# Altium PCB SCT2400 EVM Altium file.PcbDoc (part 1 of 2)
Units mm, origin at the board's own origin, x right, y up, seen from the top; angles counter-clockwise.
Board outline 45.2 x 80.2 mm, 4 copper layers (Top Layer, Signal Layer 1, Signal Layer 2, Bottom Layer), stack 0.778 mm thick; 165 components, 146 nets, 619 pads, 674 vias.
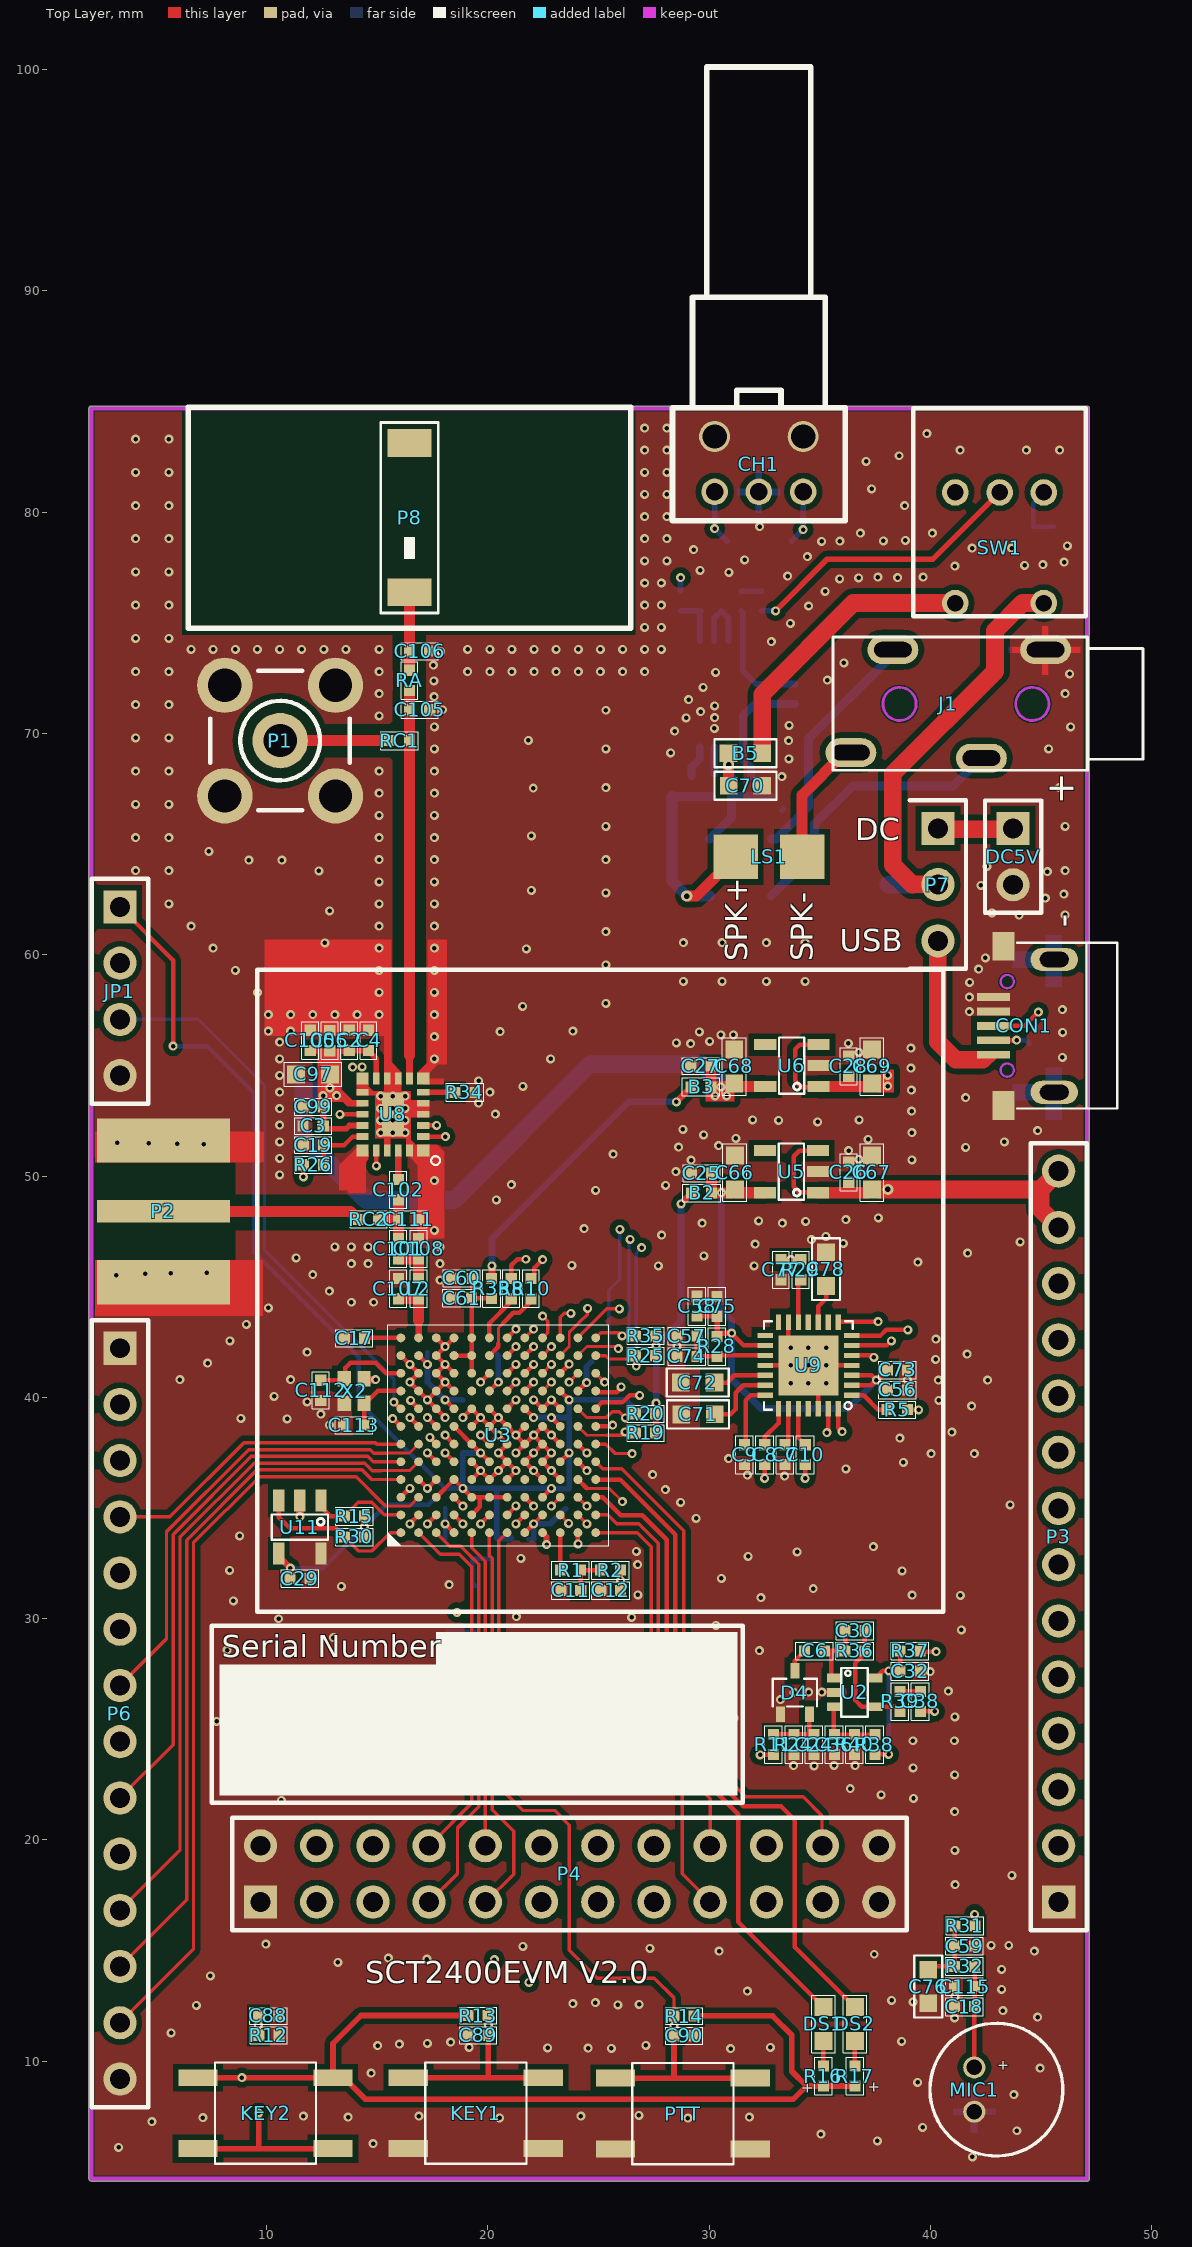
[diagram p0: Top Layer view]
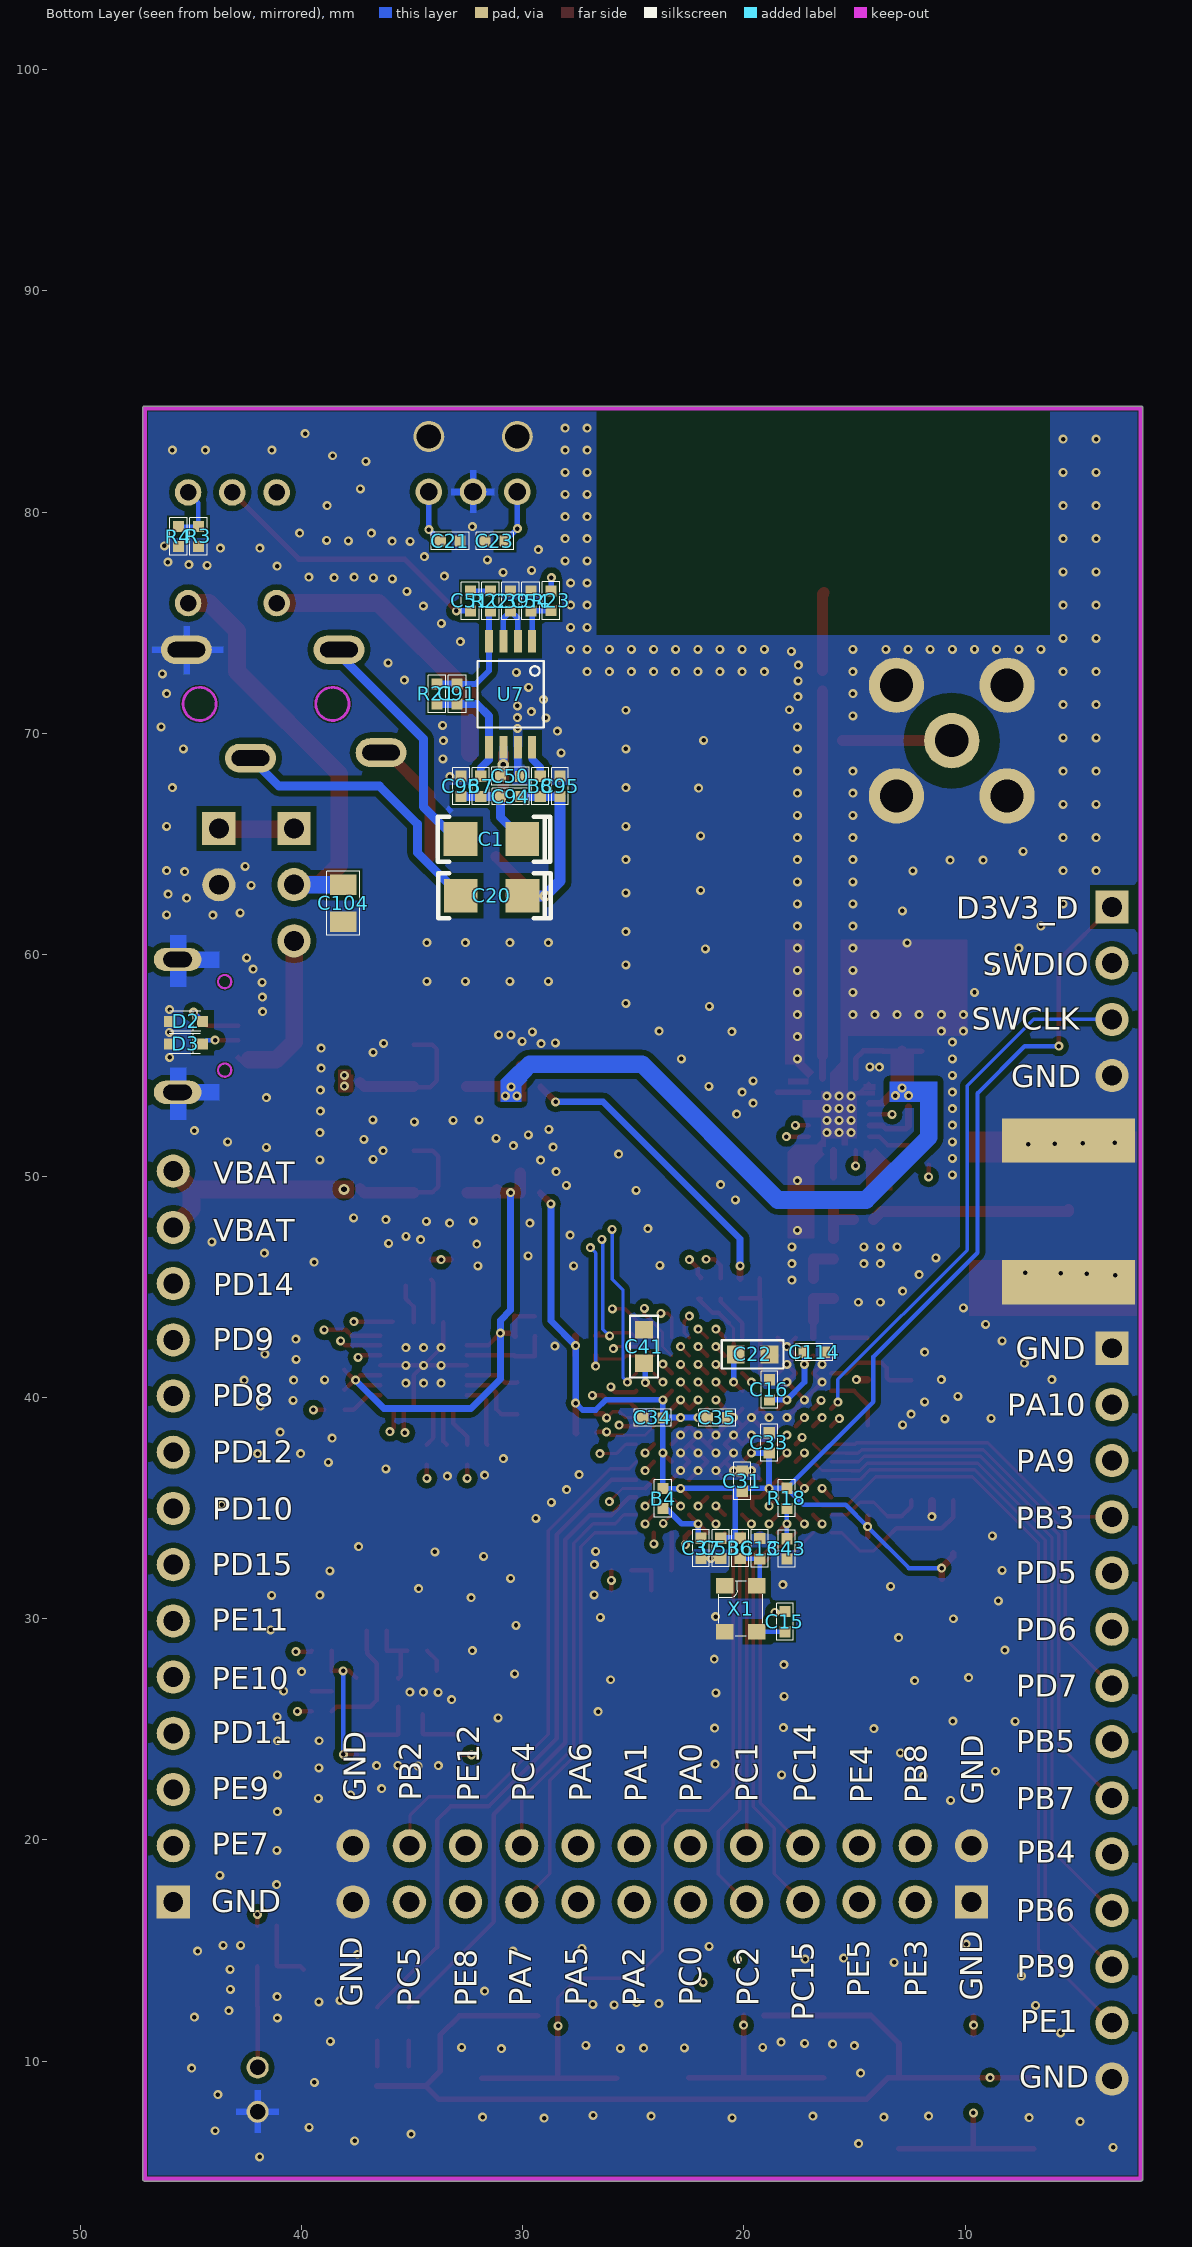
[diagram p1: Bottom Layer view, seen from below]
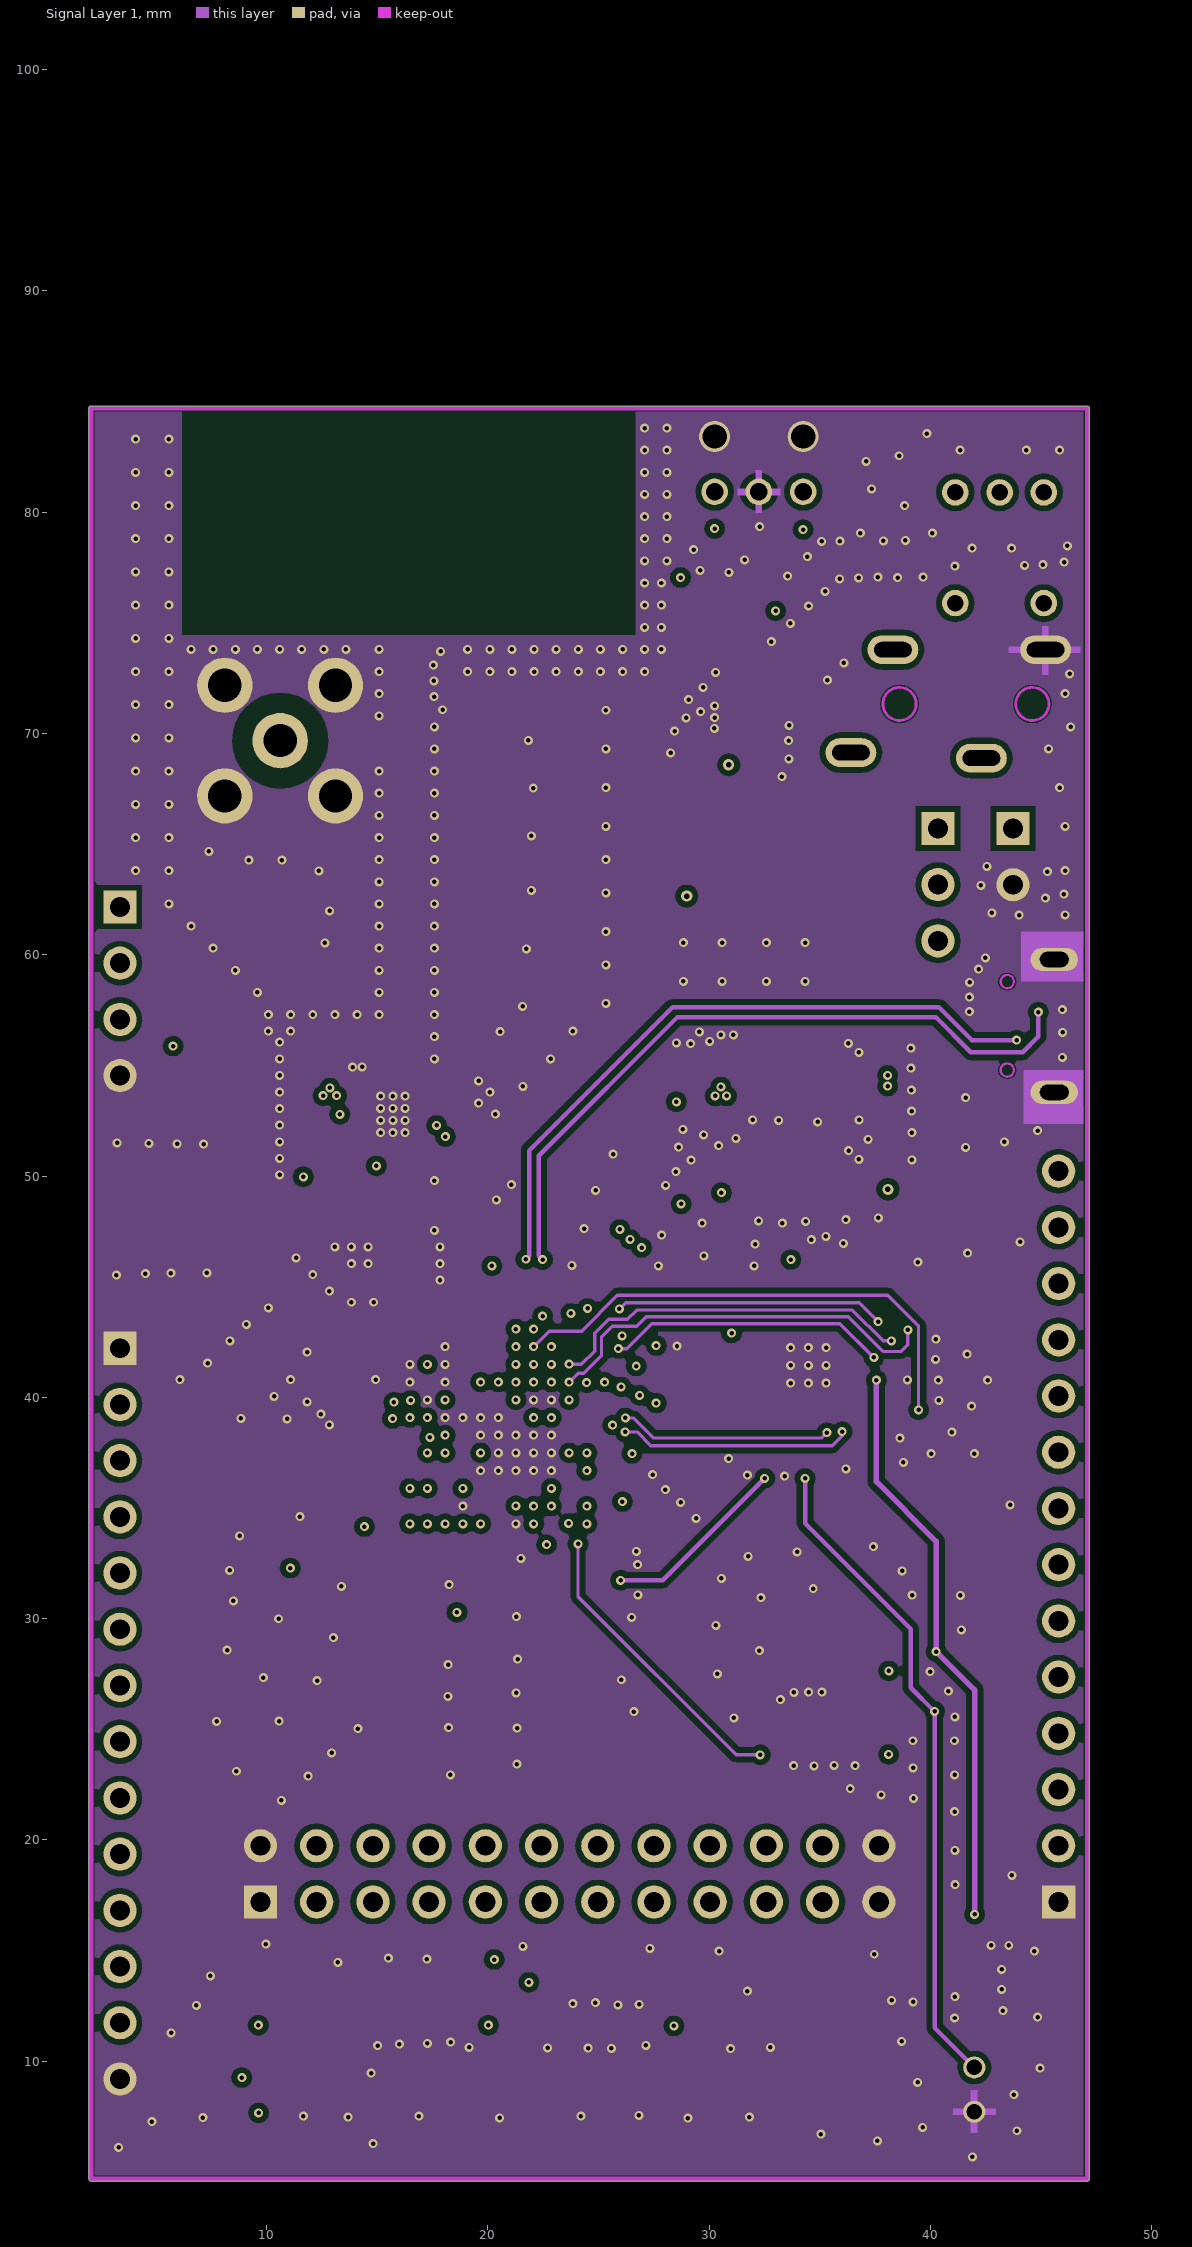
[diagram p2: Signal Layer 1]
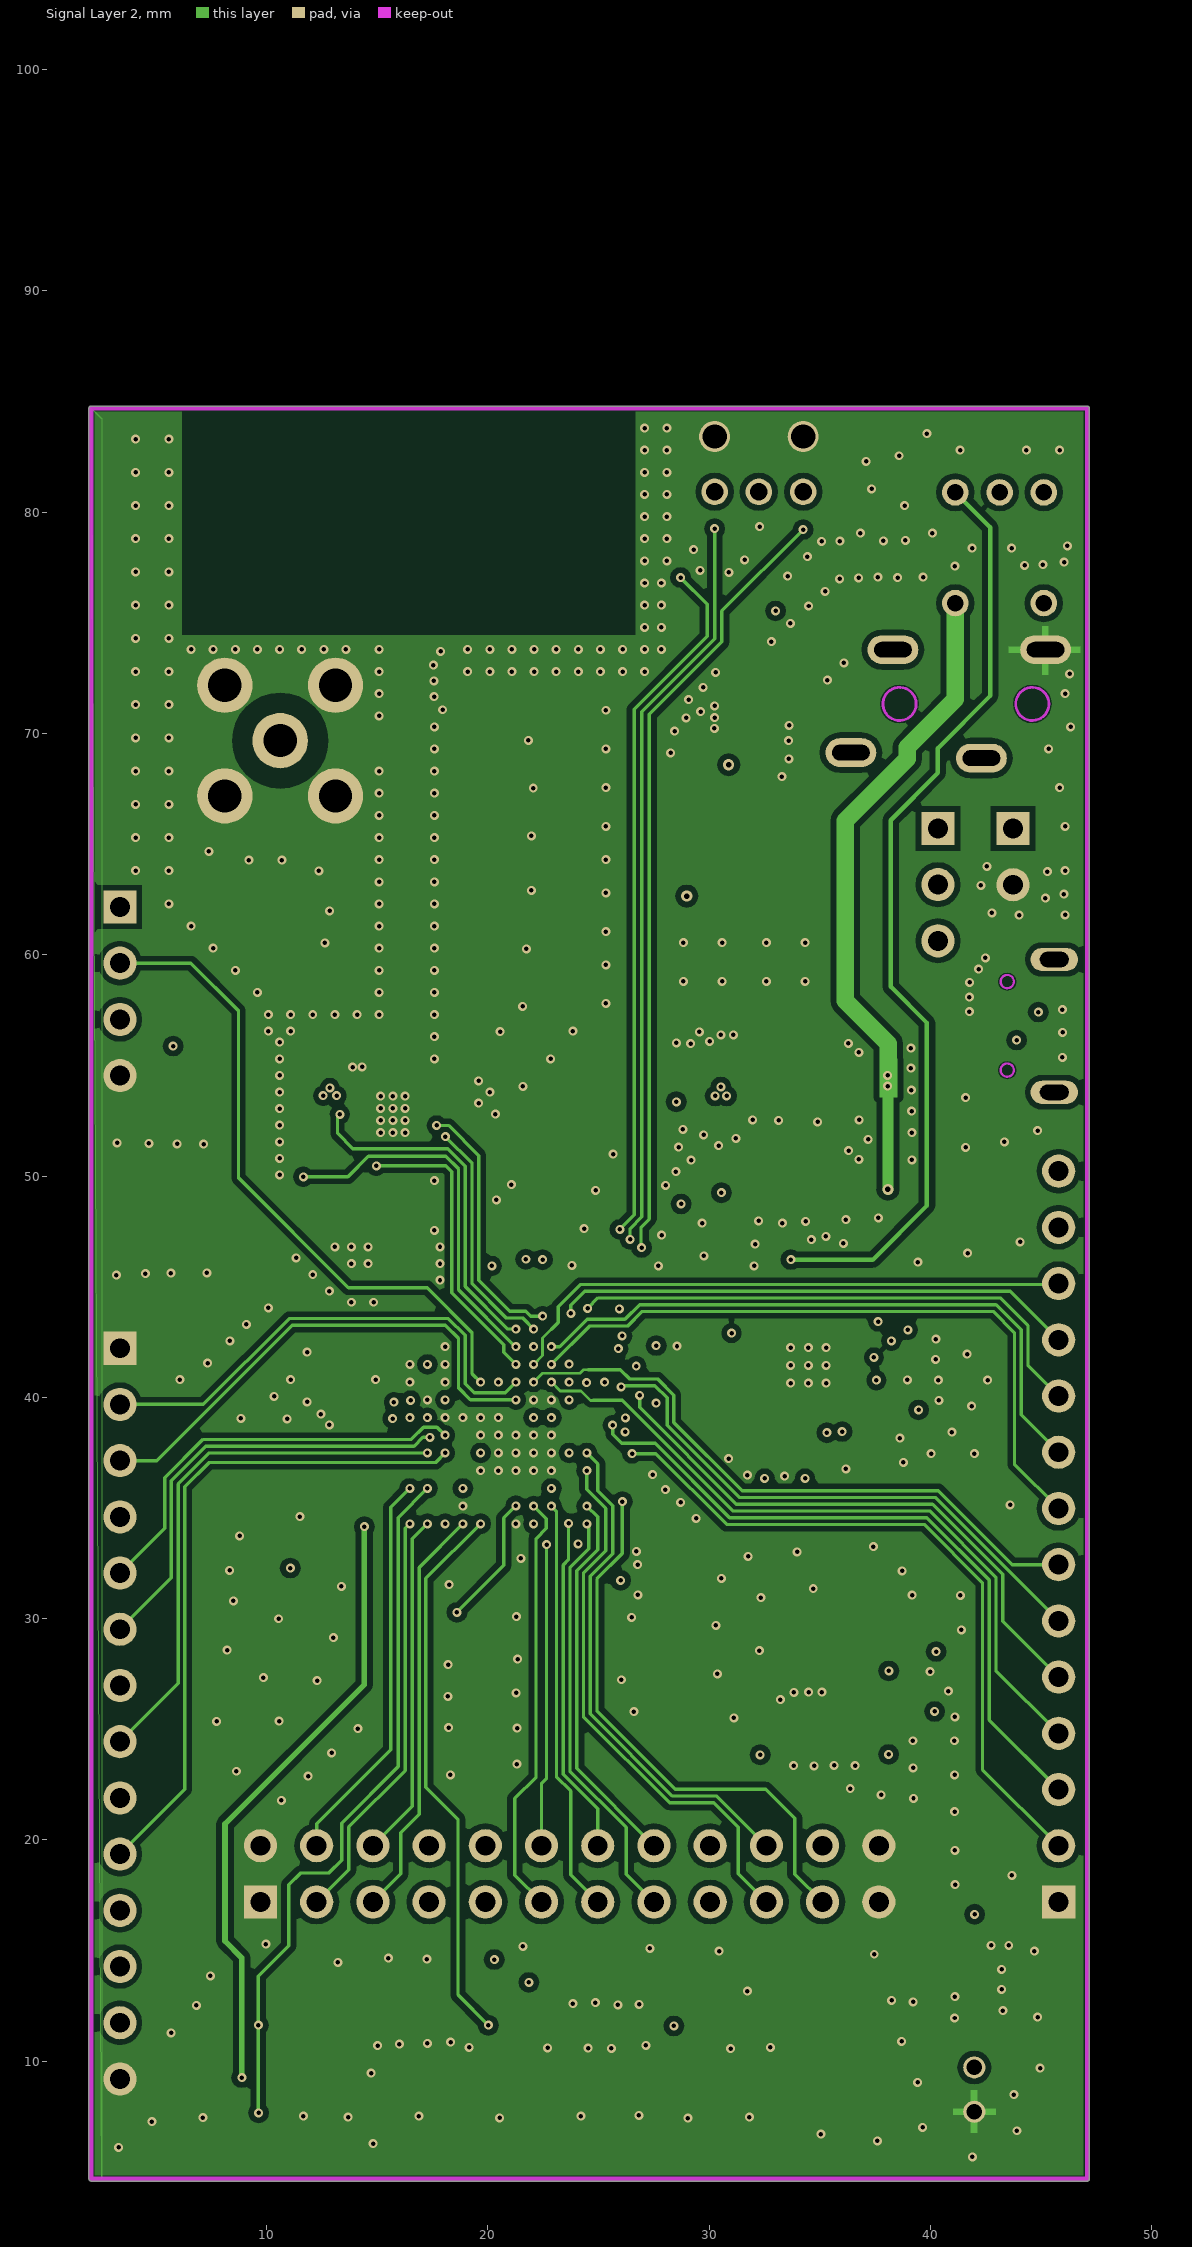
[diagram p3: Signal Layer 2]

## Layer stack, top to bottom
Top Solder: solder mask 0.0102, Solder Resist, Dk 3.5
Top Layer: signal copper 0.0356
Dielectric 1: core 0.254, FR-4, Dk 4.2
Signal Layer 1: signal copper 0.036
Dielectric 3: prepreg 0.127, Dk 4.2
Signal Layer 2: signal copper 0.036
Dielectric 2: core 0.254, Dk 4.2
Bottom Layer: signal copper 0.0356
Bottom Solder: solder mask 0.0102, Solder Resist, Dk 3.5

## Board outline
1.972,4.691 ccw(c2.074,4.691) 2.074,4.589 47.074,4.589 ccw(c47.074,4.691) 47.176,4.691 47.176,84.691 ccw(c47.074,84.691) 47.074,84.793 2.074,84.793 ccw(c2.074,84.691) 1.972,84.691

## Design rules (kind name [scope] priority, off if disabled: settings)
Clearance RF [All vs (OnLayer('Keep-Out Layer'))] p1: gap=0.051
Clearance [All] p2 off: gap=0.254
Clearance DRC [All] p3: gap=0.152 except(0.127: Track-SMDPad Track-Via)
ComponentClearance [All] p1: gap=0.051 collisioncheckmode=3 verticalgap=0.254 showdistances=FALSE
HoleSize [All] p1 off: absolutevalues=TRUE maxlimit=2.54 minlimit=0.025 maxpercent=80.000 minpercent=20.000
HoleToHoleClearance [All] p1 off: gap=0.254 allowstackedmicrovias=TRUE
MinimumSolderMaskSliver [All] p1 off: minsoldermaskwidth=0.254
PolygonConnect [All] p1: connectstyle=Direct reliefconductorwidth=0.254 reliefentries=4 polygonreliefangle="90 Angle" airgapwidth=0.254
RoutingVias [All] p1: holewidth=0.203 width=0.406 viastyle="Through Hole" minholewidth=0.203 minwidth=0.406 maxholewidth=0.508 maxwidth=1.27
SilkToBoardRegionClearance [All] p1 off:
SilkToSilkClearance [All] p1 off: silktosilkclearance=0.051
SilkToSolderMaskClearance [IsPad] p1 off: minsilkscreentomaskgap=0.254 clearancetoexposedcopper=TRUE
SolderMaskExpansion [All] p1: expansion=0.051
Width [All] p1: maxlimit=1.524 minlimit=0.127 preferedwidth=0.203
23 further rules are at their usual default settings.

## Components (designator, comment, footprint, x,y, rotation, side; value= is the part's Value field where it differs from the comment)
B2 "B601" 0402_MJ 30.111,49.241 r180 top
B3 "B601" 0402_MJ 30.084,54.033 r180 top
B4 "B601" 0402_MJ 23.659,35.874 r270 bottom
B5 "B601" 0603-mini 31.637,69.103 r0 top
B6 "NC" 0402 20.171,33.176 r90 bottom
B7 "B601" 0402 31.893,67.606 r270 bottom
B8 "B601" 0402 29.201,67.606 r270 bottom
C1 "100uF" C3216 26.574,65.215 r0 bottom
C2 "0.1uF" 0402 13.733,56.127 r90 top
C3 "1nF" 0402 12.102,52.265 r0 top
C4 "1nF" 0402 14.606,56.127 r90 top
C6 "47nF" 0402_MJ 34.306,28.541 r0 top
C7 "1uF" 0402_MJ 33.423,36.958 r90 top
C8 "1uF" 0402_MJ 32.509,36.958 r90 top
C9 "1uF" 0402_MJ 31.594,36.958 r90 top
C10 "1uF" 0402_MJ 34.338,36.958 r90 top
C11 "4.7nF" 0402_mj 23.294,31.278 r0 top
C12 "10nF" 0402_mj 25.097,31.278 r0 top
C13 "NC" 0402 19.292,33.17 r90 bottom
C15 "NC" 0402 18.149,29.867 r270 bottom
C16 "10nF" 0402 18.849,40.34 r90 bottom
C17 "10nF" 0402 13.963,42.668 r0 top
C18 "10nF" 0402_MJ 41.977,12.469 r180 top
C19 "1nF" 0402 12.113,51.401 r180 top
C20 "100uF" C3216 26.565,62.648 r0 bottom
C21 "100pF" 0402_MJ 33.725,78.694 r180 bottom
C22 "2.2uF" 0603_MJ 19.61,41.939 r0 bottom
C23 "100pF" 0402_MJ 30.804,78.694 r0 bottom
C24 "1uF" 0402_MJ 34.738,24.757 r270 top
C25 "0.1uF" 0402 29.658,50.133 r180 top
C26 "0.1uF" 0402 36.309,50.174 r90 top
C27 "0.1uF" 0402 29.627,54.973 r180 top
C28 "0.1uF" 0402 36.306,54.969 r90 top
C29 "0.1uF" 0402_MJ 11.051,31.811 r0 top
C30 "56pF" 0402_MJ 36.135,29.456 r0 top
C31 "0.1uF" 0402 20.074,36.219 r90 bottom
C32 "1uF" 0402_MJ 38.624,27.627 r0 top
C33 "0.1uF" 0402 18.858,37.948 r90 bottom
C34 "0.1uF" 0402 24.122,39.072 r180 bottom
C35 "0.1uF" 0402 21.202,39.081 r180 bottom
C36 "1uF" 0402_MJ 35.653,24.757 r270 top
C37 "0.1uF" 0402 21.942,33.179 r90 bottom
C38 "0.1uF" 0402_MJ 39.539,26.712 r270 top
C39 "1uF" 0402_mj 30.547,75.531 r90 bottom
C41 "2.2uF" 0603_MJ 24.518,42.296 r270 bottom
C43 "0.1uF" 0402 18.062,33.152 r270 bottom
C50 "0.1uF" 0402_mj 31.004,68.064 r180 bottom
C51 "0.1uF" 0402_MJ 32.366,75.538 r90 bottom
C53 "NC" 0402 21.051,33.176 r270 bottom
C54 "NC" 0402_MJ 29.633,75.531 r90 bottom
C55 "0.1uF" 0402 12.853,56.124 r90 top
C56 "10nF" 0402_mj 38.058,40.333 r0 top
C57 "10nF" 0402_MJ 29.442,42.767 r180 top
C58 "10nF" 0402_mj 29.452,43.67 r90 top
C59 "0.1uF" 0402_MJ 41.088,15.206 r0 top
C60 "0.1uF" 0402 18.824,45.375 r0 top
C61 "0.1uF" 0402_MJ 18.366,44.486 r0 top
C66 "10uF" 0603 31.154,50.157 r270 top
C67 "10uF" 0603 37.349,50.164 r270 top
C68 "10uF" 0603 31.13,54.955 r270 top
C69 "10uF" 0603 37.356,54.955 r270 top
C70 "10uF" 0603-MINI 31.637,67.638 r180 top
C71 "10uF" 0603-MINI 29.492,39.234 r180 top
C72 "10uF" 0603-MINI 29.481,40.669 r0 top
C73 "1uF" 0402_MJ 38.057,41.24 r0 top
C74 "1uF" 0402_MJ 28.545,41.85 r0 top
C75 "1uF" 0402_MJ 30.354,43.665 r90 top
C76 "10uF" 0603-MINI 39.894,13.377 r270 top
C77 "22nF" 0402 33.245,45.772 r90 top
C78 "10uF" 0603-MINI 35.277,45.797 r90 top
C88 "100pF" 0402 10.085,12.047 r0 top
C89 "100pF" 0402 19.554,11.179 r180 top
C90 "100pF" 0402 28.865,11.156 r0 top
C91 "NC" 0402_MJ 32.958,72.233 r270 bottom
C94 "NC" 0402 30.547,67.149 r180 bottom
C95 "NC" 0402 28.312,67.606 r90 bottom
C96 "NC" 0402 32.782,67.606 r90 bottom
C97 "4.7uF" 0603 12.096,54.598 r0 top
C99 "0.1uF" 0402 12.107,53.132 r0 top
C100 "1nF" 0402 11.976,56.127 r90 top
C101 "100pF" 0402 15.953,46.716 r90 top
C102 "0R" 0402 15.953,49.388 r90 top
C104 "22uF/10V" 0805 38.104,63.169 r270 bottom
C105 "NC" 0402 16.912,71.073 r0 top
C106 "NC" 0402 16.912,73.722 r180 top
C107 "1.2pF" 0402 15.953,44.918 r90 top
C108 "1.2pF" 0402 16.868,46.715 r270 top
C111 "NC" 0402 16.411,48.042 r180 top
C112 "NC" 0402 12.448,40.32 r90 top
C113 "NC" 0402 13.947,38.746 r180 top
C114 "470nF" 0402 16.817,42.042 r0 bottom
C115 "100pF" 0402_MJ 41.088,13.377 r0 top
CH1 "Channel Switch" CH_SW_MINI 30.242,80.916 r0 top
CON1 "microUSB" "MICRO USB" 42.842,56.786 r90 top
D2 "VAR" HVC131_SMALL 45.958,56.987 r90 bottom
D3 "VAR" HVC131_SMALL 45.965,55.973 r90 bottom
D4 "1SS372" 1ss372 33.875,26.662 r0 top
DC5V "Header 2" HDR1X2 43.73,65.701 r270 top
DS1 "G_LED" 0603 35.158,11.689 r90 top
DS2 "R_LED" 0603 36.581,11.689 r90 top
J1 "" ST-320 45.199,73.784 r180 top
JP1 "JTAG" HDR1X4 3.372,62.159 r270 top
KEY1 "KEY1" "SW SMD" 19.454,7.656 r180 top
KEY2 "KEY2" "SW SMD" 9.95,7.654 r0 top
L2 "3.9nH" 0402 16.868,44.918 r90 top
LS1 "Speaker" SPK_CON 31.197,64.427 r0 top
MIC1 "MIC" MIC_6MM 41.977,9.72 r90 top
P1 "SMB" SMB_V-RJ45 10.612,69.675 r180 top
P2 "SMB" SMA-2 5.337,48.403 r90 top
P3 "Header 14" HDR1X14 45.79,17.201 r90 top
P4 "Header 12X2" HDR2X12 9.722,17.201 r0 top
P6 "Header 14" HDR1X14 3.372,42.221 r270 top
P7 "Header 3" HDR1X3 40.333,65.709 r270 top
P8 "Antenna" 2450AT43A100 16.457,79.748 r90 top
PTT "PTT" "SW SMD" 28.81,7.638 r180 top
R1 "4.7K" 0402_MJ 24.183,32.192 r180 top
R2 "4.7K" 0402_MJ 25.986,32.192 r180 top
R3 "10R" 0402_MJ 44.651,79.35 r270 bottom
R4 "100R" 0402_MJ 45.559,79.341 r270 bottom
R5 "0R" 0402 38.503,39.447 r180 top
R8 "22R" 0402 21.059,44.918 r90 top
R10 "22R" 0402 21.948,44.918 r90 top
R11 "1K" 0402_MJ 32.909,23.868 r90 top
R12 "10K" 0402 10.097,11.18 r180 top
R13 "10K" 0402 19.554,12.068 r180 top
R14 "10K" 0402 28.865,12.045 r0 top
R15 "10K" 0402_MJ 13.515,34.631 r0 top
R16 "1.5K" 0402_MJ 35.158,9.784 r270 top
R17 "1.5K" 0402_MJ 36.581,9.784 r270 top
R18 "47K" 0402 18.062,35.438 r270 bottom
R19 "5.1K" 0402 27.126,38.39 r180 top
R20 "5.1K" 0402 27.122,39.254 r180 top
R21 "68K" 0402_MJ 33.875,72.24 r270 bottom
R22 "20K" 0402_MJ 31.45,76.431 r270 bottom
R23 "1K" 0402_MJ 28.718,76.446 r270 bottom
R24 "120K" 0402_MJ 33.824,24.757 r270 top
R25 "10K" 0402 27.123,41.877 r0 top
R26 "1.2K" 0402 12.113,50.512 r0 top
R28 "10R" 0402_MJ 30.35,41.855 r90 top
R29 "1K" 0402 34.134,45.772 r90 top
R30 "10K" 0402_MJ 13.515,33.691 r0 top
R31 "1K" 0402_MJ 42.003,16.121 r180 top
R32 "2.2K" 0402_MJ 41.088,14.292 r0 top
R33 "0R" 0402_MJ 20.17,45.375 r270 top
R34 "51R" 0402_MJ 19.408,53.782 r180 top
R35 "10K" 0402 27.123,42.779 r0 top
R36 "1M" 0402_MJ 37.024,28.541 r180 top
R37 "22R" 0402_MJ 38.624,28.541 r0 top
R38 "10K" 0402_MJ 37.481,24.757 r270 top
R39 "15K" 0402_MJ 38.624,26.712 r270 top
R40 "10K" 0402_MJ 36.567,23.868 r90 top
RA "0R" 0402 16.455,72.394 r90 top
RC1 "NC" 0402_MJ 15.557,69.674 r0 top (schematic designator RC)
RC2 "NC" 0402 14.607,48.042 r180 top
SW1 "R08740NS" PA_SW_SHRINK 43.12,80.891 r0 top
U2 "SGM721XC5" SC-88A 35.627,27.322 r270 top
U3 "SCT2400" SCT3268 15.468,33.288 r90 top (schematic designator U6)
U5 "FP614633S5GTR" SOT-25 34.921,49.246 r90 top
U6 "FP614633S5GTR" SOT-25 34.932,54.037 r90 top
U7 "LM4890" MSOP-8 30.547,71.772 r270 bottom
U8 "SKY66112-11" SKY66112 15.705,52.786 r180 top
U9 "ES8388S" QFN28-4*4 34.48,41.444 r180 top
U11 "BM24C32" SOT-25 12.448,35.342 r180 top
X1 "NC" SMD2520 20.868,31.488 r180 bottom
X2 "52MHz" SMD1612 14.404,39.736 r90 top

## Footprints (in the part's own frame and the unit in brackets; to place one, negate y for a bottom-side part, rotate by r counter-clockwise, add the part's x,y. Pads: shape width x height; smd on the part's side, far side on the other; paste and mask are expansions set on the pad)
1ss372 [mm]
  rect 0.4x0.7 smd: 1(-0.65,-0.975) 2(0.65,-0.975) 3(0,0.975)
  silkscreen extent -1,-0.63 1,0.63
0402 [mil]
  rect 20x20 smd: 1(-18,0) 2(18,0)
  silkscreen extent -33,-15 33,15
0402_MJ [mm]
  rect 0.5x0.5 smd: 1(0,0) 2(0.9,0)
  silkscreen extent -0.4,-0.4 1.3,0.4
0402_mj [mm]
  rect 0.5x0.5 smd: 1(0,0) 2(0.9,0)
  silkscreen extent -0.4,-0.4 1.3,0.4
0603 [mil]
  rect 32x32 smd: 1(-30,0) 2(30,0)
  silkscreen extent -51,-21 51,21
0603-mini [mm]
  rect 0.8x0.8 smd: 1(-0.762,0) 2(0.759,0.004)
  silkscreen extent -1.4,-0.64 1.4,0.64
0603-MINI [mm]
  rect 0.8x0.8 smd: 1(-0.762,0) 2(0.759,0.004)
  silkscreen extent -1.4,-0.64 1.4,0.64
0603_MJ [mm]
  rect 0.8x0.8 smd: 1(-0.76,-0.002) 2(0.76,0.002)
  silkscreen extent -1.4,-0.64 1.4,0.63
0805 [mm]
  rect 0.925x1.2 smd: 1(0,0) 2(1.675,0)
  silkscreen extent -0.61,-0.75 2.29,0.75
2450AT43A100 [mm]
  rect 1.25x2 smd: 1(-3.375,0) 2(3.375,0)
  silkscreen extent -5,-10 5,10
C3216 [mil]
  rect 60x60 smd: 1(135.64,-0.51) 2(245.64,-0.51)
  silkscreen extent 86,-41 286,39
CH_SW_MINI [mm]
  round 1.2 hole 0.8: 1(0,0) 2(2,0) 3(4,0)
  round 1.4 hole 1.1: 4(0,2.5) 5(4,2.5)
  silkscreen extent -1.9,-1.3 5.9,19.2
HDR1X2 [mm] "Connector; Header; 2 Position"
  rect 1.5x1.5 hole 0.9: 1(0,0)
  round 1.5 hole 0.9: 2(2.54,0)
  silkscreen extent -1.27,-1.27 3.81,1.27
HDR1X3 [mm] "Connector; Header; 3 Position"
  rect 1.5x1.5 hole 0.9: 1(0,0)
  round 1.5 hole 0.9: 2(2.54,0) 3(5.08,0)
  silkscreen extent -1.27,-1.27 6.35,1.27
HDR1X4 [mm] "Connector; Header; 4 Position"
  rect 1.5x1.5 hole 0.9: 1(0,0)
  round 1.5 hole 0.9: 2(2.54,0) 3(5.08,0) 4(7.62,0)
  silkscreen extent -1.27,-1.27 8.89,1.27
HDR1X14 [mm] "Connector; Header; 14 Position"
  rect 1.5x1.5 hole 0.9: 1(0,0)
  round 1.5 hole 0.9: 2(2.54,0) 3(5.08,0) 4(7.62,0) 5(10.16,0) 6(12.7,0) 7(15.24,0) 8(17.78,0) 9(20.32,0) 10(22.86,0) 11(25.4,0) 12(27.94,0) 13(30.48,0) 14(33.02,0)
  silkscreen extent -1.27,-1.27 34.29,1.27
HDR2X12 [mm] "Connector; Header; 12x2 Position"
  rect 1.5x1.5 hole 0.9: 1(0,0)
  round 1.5 hole 0.9: 2(0,2.54) 3(2.54,0) 4(2.54,2.54) 5(5.08,0) 6(5.08,2.54) 7(7.62,0) 8(7.62,2.54) 9(10.16,0) 10(10.16,2.54) 11(12.7,0) 12(12.7,2.54) 13(15.24,0) 14(15.24,2.54) 15(17.78,0) 16(17.78,2.54) 17(20.32,0) 18(20.32,2.54) 19(22.86,0) 20(22.86,2.54) 21(25.4,0) 22(25.4,2.54) 23(27.94,0) 24(27.94,2.54)
  silkscreen extent -1.27,-1.27 29.21,3.81
HVC131_SMALL [mm]
  rect 0.5x0.5 smd: 1(0,0) 2(0,-1.5)
  silkscreen extent -0.45,-1.4 0.45,0
MIC_6MM [mm]
  round 1 hole 0.7: 1(0,0) 2(-2,0)
  silkscreen extent -4,-4 2,2
"MICRO USB" [mm]
  rect 0.35x1.5 smd mask+0.05: 1(-1.3,0) 2(-0.65,0) 3(0,0) 4(0.65,0) 4(1.3,0)
  oval 1.05x2.15 hole 0.7 slot 1.3 at 90 deg mask+0.05: 5(-3,-2.75) 5(3,-2.75)
  rect 1.3x1 smd mask+0.05: 6(-3.6,-0.45) 6(3.6,-0.45)
  Keep-Out Layer circle w0.1: c-2,-0.625 r0.3
  Keep-Out Layer circle w0.1: c2,-0.625 r0.3
  silkscreen extent -3.74,-5.6 3.76,-1.08
MSOP-8 [mm]
  rect 1.02x0.36 smd: 1(-2.4,0.975) 2(-2.4,0.325) 3(-2.4,-0.325) 4(-2.4,-0.975) 5(2.4,-0.975) 6(2.4,-0.325) 7(2.4,0.325) 8(2.4,0.975)
  silkscreen extent -1.5,-1.5 1.5,1.5
PA_SW_SHRINK [mm]
  round 1.2 hole 0.75: 1(2,0) 2(0,0) 3(-2,0) 4(2,-5) 5(-2,-5)
  silkscreen extent -3.9,-5.6 3.9,3.8
QFN28-4*4 [mm]
  rect 0.7x0.24 smd: 1(-1.95,1.35) 2(-1.95,0.9) 3(-1.95,0.45) 4(-1.95,0) 5(-1.95,-0.45) 6(-1.95,-0.9) 7(-1.95,-1.35) 15(1.95,-1.35) 16(1.95,-0.9) 17(1.95,-0.45) 18(1.95,0) 19(1.95,0.45) 20(1.95,0.9) 21(1.95,1.35)
  rect 0.24x0.7 smd: 8(-1.35,-1.95) 9(-0.9,-1.95) 10(-0.45,-1.95) 11(0,-1.95) 12(0.45,-1.95) 13(0.9,-1.95) 14(1.35,-1.95) 22(1.35,1.95) 23(0.9,1.95) 24(0.45,1.95) 25(0,1.95) 26(-0.45,1.95) 27(-0.9,1.95) 28(-1.35,1.95)
  rect 2.7x2.7 smd: 29(0,0)
  silkscreen extent -2,-2 2,2
SC-88A [mm]
  rect 0.4x0.6 smd: 1(0,0) 2(0.65,0) 3(1.3,0) 4(1.3,1.9) 5(0,1.9)
  silkscreen extent -0.45,0.34 1.75,1.54
SCT3268 [mm]
  round 0.4 smd: A1(0.6,-0.6) A2(1.4,-0.6) A3(2.2,-0.6) A4(3,-0.6) A5(3.8,-0.6) A6(4.6,-0.6) A7(5.4,-0.6) A8(6.2,-0.6) A9(7,-0.6) A10(7.8,-0.6) A11(8.6,-0.6) A12(9.4,-0.6) B1(0.6,-1.4) B2(1.4,-1.4) B3(2.2,-1.4) B4(3,-1.4) B5(3.8,-1.4) B6(4.6,-1.4) B7(5.4,-1.4) B8(6.2,-1.4) B9(7,-1.4) B10(7.8,-1.4) B11(8.6,-1.4) B12(9.4,-1.4) C1(0.6,-2.2) C2(1.4,-2.2) C3(2.2,-2.2) C4(3,-2.2) C5(3.8,-2.2) C6(4.6,-2.2) C7(5.4,-2.2) C8(6.2,-2.2) C9(7,-2.2) C10(7.8,-2.2) C11(8.6,-2.2) C12(9.4,-2.2) D1(0.6,-3) D2(1.4,-3) D3(2.2,-3) D4(3,-3) D5(3.8,-3) D6(4.6,-3) D7(5.4,-3) D8(6.2,-3) D9(7,-3) D10(7.8,-3) D11(8.6,-3) D12(9.4,-3) E1(0.6,-3.8) E2(1.4,-3.8) E3(2.2,-3.8) E4(3,-3.8) E5(3.8,-3.8) E6(4.6,-3.8) E7(5.4,-3.8) E8(6.2,-3.8) E9(7,-3.8) E10(7.8,-3.8) E11(8.6,-3.8) E12(9.4,-3.8) F1(0.6,-4.6) F2(1.4,-4.6) F3(2.2,-4.6) F4(3,-4.6) F5(3.8,-4.6) F6(4.6,-4.6) F7(5.4,-4.6) F8(6.2,-4.6) F9(7,-4.6) F10(7.8,-4.6) F11(8.6,-4.6) F12(9.4,-4.6) G1(0.6,-5.4) G2(1.4,-5.4) G3(2.2,-5.4) G4(3,-5.4) G5(3.8,-5.4) G6(4.6,-5.4) G7(5.4,-5.4) G8(6.2,-5.4) G9(7,-5.4) G10(7.8,-5.4) G11(8.6,-5.4) G12(9.4,-5.4) H1(0.6,-6.2) H2(1.4,-6.2) H3(2.2,-6.2) H4(3,-6.2) H5(3.8,-6.2) H6(4.6,-6.2) H7(5.4,-6.2) H8(6.2,-6.2) H9(7,-6.2) H10(7.8,-6.2) H11(8.6,-6.2) H12(9.4,-6.2) J1(0.6,-7) J2(1.4,-7) J3(2.2,-7) J4(3,-7) J5(3.8,-7) J6(4.6,-7) J7(5.4,-7) J8(6.2,-7) J9(7,-7) J10(7.8,-7) J11(8.6,-7) J12(9.4,-7) K1(0.6,-7.8) K2(1.4,-7.8) K3(2.2,-7.8) K4(3,-7.8) K5(3.8,-7.8) K6(4.6,-7.8) K7(5.4,-7.8) K8(6.2,-7.8) K9(7,-7.8) K10(7.8,-7.8) K11(8.6,-7.8) K12(9.4,-7.8) L1(0.6,-8.6) L2(1.4,-8.6) L3(2.2,-8.6) L4(3,-8.6) L5(3.8,-8.6) L6(4.6,-8.6) L7(5.4,-8.6) L8(6.2,-8.6) L9(7,-8.6) L10(7.8,-8.6) L11(8.6,-8.6) L12(9.4,-8.6) M1(0.6,-9.4) M2(1.4,-9.4) M3(2.2,-9.4) M4(3,-9.4) M5(3.8,-9.4) M6(4.6,-9.4) M7(5.4,-9.4) M8(6.2,-9.4) M9(7,-9.4) M10(7.8,-9.4) M11(8.6,-9.4) M12(9.4,-9.4)
  silkscreen extent -0.02,-10 10,0.01
SKY66112 [mm]
  rect 1x2 smd: 0(0,0)
  rect 0.55x0.55 smd: 1(-1.375,1.625) 7(-1.375,-1.625) 12(1.375,-1.625) 18(1.375,1.625)
  rect 0.55x0.3 smd: 2(-1.375,1) 3(-1.375,0.5) 4(-1.375,0) 5(-1.375,-0.5) 6(-1.375,-1) 13(1.375,-1) 14(1.375,-0.5) 15(1.375,0) 16(1.375,0.5) 17(1.375,1)
  rect 0.3x0.55 smd: 8(-0.75,-1.625) 9(-0.25,-1.625) 10(0.25,-1.625) 11(0.75,-1.625) 19(0.75,1.625) 20(0.25,1.625) 21(-0.25,1.625) 22(-0.75,1.625)
  silkscreen extent -2.13,1.89 -1.73,2.29
SMA-2 [mm]
  rect 1.016x6 smd: 1(0,0)
  rect 2x6 smd: 2(-3.2,0) 2(3.2,0)
  rect 2x6 smd far side: 2(-3.2,0) 2(3.2,0)
SMB_V-RJ45 [mm] "Connector; SMB Straight"
  round 2.5 hole 1.5: 1(0,0) 2(-2.5,2.5) 2(-2.5,-2.5) 2(2.5,2.5) 2(2.5,-2.5)
  silkscreen extent -3.15,-3.15 3.15,3.15
SMD1612 [mm]
  rect 0.7x0.6 smd mask+0.05: 1(0,0) 2(1.1,0) 3(1.1,0.9) 4(0,0.9)
SMD2520 [mm]
  rect 0.8x0.68 smd: 1(0,0) 2(0,-2.08) 3(1.45,-2.08) 4(1.45,0)
  silkscreen extent -0.28,-2.29 1.73,0.21
SOT-25 [mm]
  rect 0.5x1 smd: 1(0,0) 2(0.95,0) 3(1.9,0) 4(1.9,2.4) 5(0,2.4)
  silkscreen extent -0.32,0.64 2.22,1.78
SPK_CON [mm]
  rect 2x2 smd: 1(0,0.001) 2(3,0)
ST-320 [mm]
  oval 2.3x1.3 hole 0.7 slot 1.7 at 0 deg: 1(0,0) 2(2.9,4.9) 3(8.8,4.65) 4(6.9,0)
  Keep-Out Layer circle w0.127: c0.6,2.45 r0.75
  Keep-Out Layer circle w0.127: c6.6,2.45 r0.75
  silkscreen extent -4.4,-0.58 9.6,5.45
"SW SMD" [mil] "贴片按钮"
  rect 70x30 smd: 1(-120,-63) 1(120,-63) 2(-120,63) 2(120,63)
  silkscreen extent -90,-90 90,90

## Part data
B2 B3 B4 B5 B6 B7 B8: library part B
C1 C20 C104: library part "Cap Pol3", "Polarized Capacitor (Surface Mount)"
C2 C3 C4 C19 C97 C99 C100 C101 C102 C105 C106 C107 C108 C111 C112 C113 C114 RC2: library part Cap, "Capacitor"
C6 C24 C30 C32 C36 C38 C115: library part "Cap Semi_1", "Capacitor (Semiconductor SIM Model)"
C7 C8 C9 C10 C11 C12 C13 C15 C16 C17 C18 C21 C22 C23 C25 C26 C27 C28 C29 C31 C33 C34 C35 C37 C39 C41 C43 C50 C51 C53 C54 C55 C56 C57 C58 C59 C60 C61 C66 C67 C68 C69 C70 C71 C72 C73 C74 C75 C76 C77 C78 C88 C89 C90 C91 C94 C95 C96: library part "Cap Semi", "Capacitor (Semiconductor SIM Model)"
CH1: library part "Header 5H", "Header, 5-Pin,  Right Angle"
CON1: library part MINI_USB
D2 D3: library part "D Zener", "Zener Diode"
D4: library part "REC DIODE"
DC5V: "Header, 2-Pin"
DS1 DS2: library part LED2, "Typical RED, GREEN, YELLOW, AMBER GaAs LED"
J1: library part "Phonejack Stero SW", "3-Conductor Jack with 2 break contacts (normals) and 1 auxiliary make contact"
JP1: library part "Header 4", "Header, 4-Pin"
KEY1 KEY2 PTT: library part SW-PB
L2 RA: library part Inductor, "Inductor"
LS1: "Loudspeaker"
MIC1: library part Mic1, "Microphone"
P1 P2: "SMB Straight Connector"
P3 P6: "Header, 14-Pin"
P4: "Header, 12-Pin, Dual row"
P7: "Header, 3-Pin"
P8: "Generic Antenna"
R1 R2 R3 R4 R11 R15 R16 R17 R21 R22 R23 R24 R28 R29 R30 R31 R32 R34 R36 R37 R38 R39 R40 RC1: library part "Res Semi", "Semiconductor Resistor"
R5 R8 R10 R12 R13 R14 R18 R19 R20 R25 R26 R33 R35: library part Res1, "Resistor"
SW1: library part SWITCH_POWER
U2: library part SGM721
U5 U6: library part LCO_SOT25, "LDO SOT25 封装, CE为控制端"
U7: library part TDA8541
U11: library part EEPROM
X1: library part TCXO_12.8MHZ
X2: library part NX2016SA-52M, "XTAL with GND"

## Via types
v1: diameter 0.406, hole 0.203, Top Layer to Bottom Layer, tented both sides, 667 vias
v2: diameter 0.406, hole 0.203, Top Layer to Bottom Layer, tented top, 4 vias
v3: diameter 0.508, hole 0.254, Top Layer to Bottom Layer, tented both sides, 3 vias

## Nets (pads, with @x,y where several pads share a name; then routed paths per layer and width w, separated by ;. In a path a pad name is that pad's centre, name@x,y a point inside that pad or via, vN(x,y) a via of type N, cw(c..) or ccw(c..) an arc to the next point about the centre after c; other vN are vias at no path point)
A3V3: B2.1 C25.1 C56.1 C58.1 C66.2 C73.1 C75.1 R28.2 R31.1 R37.2 U5.5 U9.2 U9.3 U9.16 | length 55.2
  Top Layer w0.203: C58.1@29.452,43.67 29.457,43.665 C75.1@30.354,43.665 ; R28.2@30.354,42.854 R28.2@30.402,42.807 ; v1(31.007,42.902) 31.564,42.344 U9.16@32.53,42.344 ; U9.2@36.43,40.544 37.319,40.544 v1(37.551,40.775) ; U9.3@36.43,40.994 37.332,40.994 v1(37.551,40.775) ; C73.1@38.057,41.24 v1@37.592,40.775 ; C56.1@38.058,40.333 37.616,40.775 v1@37.592,40.775 ; R37.2@39.524,28.541 39.552,28.514 v1(40.253,28.514) ; v1(41.992,16.642) 42.003,16.631 R31.1@42.003,16.121 ; v1(37.551,40.775) v1@37.592,40.775
  Top Layer w0.254: R28.2@30.35,42.755 R28.2@30.354,42.759 ; C75.1@30.354,43.665 30.354,42.854 R28.2@30.354,42.759 ; v1(31.007,42.902) 30.497,42.902 R28.2@30.354,42.759
  Top Layer w0.381: C66.2@31.03,49.248 31.146,49.242 C66.2@31.32,49.233
  Top Layer w0.5: C25.1@30.115,50.133 30.111,50.129 B2.1@30.111,49.241 30.999,49.241 C66.2@31.154,49.395 ; C66.2@31.238,49.246 U5.5@32.521,49.246
  Signal Layer 1 w0.254: v1(37.551,40.775) 37.551,36.193 40.253,33.491 v1(40.253,28.514) 41.992,26.775 v1(41.992,16.642)
  Bottom Layer w0.305: v1(30.548,49.247) 30.548,43.94 31.007,43.482 v1(31.007,42.902) 31.007,40.833 32.34,39.5 36.275,39.5 v1(37.551,40.775)
ADCD: U3.L12 U9.8 | length 16.3
  Top Layer w0.152: U3.L12@24.068,42.688 25.377,43.998 v1(25.944,43.998)
  Top Layer w0.203: U9.8@35.874,43.425 v1(37.633,43.425)
  Signal Layer 1 w0.152: v1(25.944,43.998) 26.226,44.281 36.777,44.281 v1(37.633,43.425)
AF_EN: R23.1 U3.M10 | length 40.1
  Top Layer w0.152: U3.M10@24.868,41.088 v1(25.268,40.688)
  Signal Layer 2 w0.152: v1(25.96,47.588) 25.96,47.55 25.937,47.573 26.613,48.249 26.613,71.086 29.917,74.389 29.917,75.831 v1(28.702,77.045)
  Bottom Layer w0.152: v1(25.268,40.688) 25.466,40.887 25.466,44.84 25.96,45.334 v1(25.96,47.588)
  Bottom Layer w0.254: v1(28.702,77.045) 28.702,76.462 R23.1@28.718,76.446
AF_PA: C51.1 SW1.2 | length 13
  Top Layer w0.254: v1(32.996,75.538) 35.334,77.876 40.106,77.876 SW1.2@43.12,80.891
  Bottom Layer w0.254: C51.1@32.366,75.538 v1(32.996,75.538)
AFOUT: C77.2 R29.2 SW1.3 | length 43.5
  Top Layer w0.203: C77.2@33.204,46.243 33.213,46.234 33.226,46.248 C77.2@33.245,46.229
  Top Layer w0.254: C77.2@33.245,46.229 R29.2@34.134,46.229
  Signal Layer 2 w0.203: v1(33.687,46.224) 37.396,46.224 39.84,48.668 39.84,56.919 38.195,58.564 38.195,66.083 40.333,68.221 40.333,69.336 42.69,71.693 42.69,79.32 SW1.3@41.12,80.891
BCLK: U3.L11 U9.5 | length 15.7
  Top Layer w0.127: U3.L11@24.068,41.888 24.475,42.296 25.806,42.296 v1(25.898,42.204)
  Top Layer w0.203: U9.5@36.43,41.894 37.346,41.894 v1(37.439,41.802)
  Signal Layer 1 w0.152: v1(25.898,42.204) 26.267,42.204 27.397,43.333 35.907,43.333 v1(37.439,41.802)
BEEP: C8.1 C12.2 R2.1 | length 10
  Top Layer w0.203: R2.1@25.986,32.192 25.997,32.181 v1(25.997,31.735) C12.2@25.997,31.278 ; v1(32.506,36.34) 32.506,36.955 C8.1@32.509,36.958
  Signal Layer 1 w0.203: v1(25.997,31.735) 27.901,31.735 v1(32.506,36.34)
BUSY: U3.C7 | length 0.6
  Top Layer w0.203: v2(17.268,39.088) U3.C7@17.668,38.688
CHL: U3.G10 U8.19 | length 14.7
  Top Layer w0.203: v1(14.955,50.461) U8.19@14.955,51.161 ; U3.G10@20.868,41.088 v1(21.268,41.488)
  Signal Layer 2 w0.152: v1(14.955,50.461) 18.1,50.461 18.368,50.193 18.368,44.726 20.718,42.376 20.718,42.038 v1(21.268,41.488)
CPS: U3.G12 U8.15 | length 17.4
  Top Layer w0.203: v1(13.307,52.79) 14.326,52.79 U8.15@14.33,52.786 ; U3.G12@20.868,42.688 v1(21.268,43.088)
  Signal Layer 2 w0.152: v1(13.307,52.79) 13.204,52.687 13.204,51.924 13.893,51.235 18.188,51.235 18.978,50.445 18.978,45.009 20.899,43.088 v1(21.268,43.088)
CRX: U3.H12 U8.2 | length 12.3
  Top Layer w0.152: U3.H12@21.668,42.688 v1(22.068,43.088)
  Top Layer w0.203: U8.2@17.08,51.786 v1(18.08,51.786)
  Signal Layer 2 w0.152: v1(18.08,51.786) 19.283,50.583 19.283,45.135 20.833,43.586 21.57,43.586 v1(22.068,43.088)
CSD: U3.J12 U8.3 | length 13.4
  Top Layer w0.152: U3.J12@22.468,42.688 22.7,42.921 22.7,43.433 v1(22.468,43.666)
  Top Layer w0.203: U8.3@17.08,52.286 v1(17.68,52.286)
  Signal Layer 2 w0.152: v1(17.68,52.286) 18.221,52.286 19.587,50.92 19.587,45.297 20.986,43.898 21.711,43.898 21.943,43.666 v1(22.468,43.666)
CTX: R26.1 U3.G11 | length 17.9
  Top Layer w0.203: v1(11.656,49.968) R26.1@11.656,50.512 ; U3.G11@20.868,41.888 v1(21.268,42.288)
  Signal Layer 2 w0.152: v1(11.656,49.968) 13.678,49.968 14.602,50.893 18.099,50.893 18.673,50.319 18.673,44.852 21.237,42.288 v1(21.268,42.288)
D3V3: B4.2 C37.2 U3.H1 U3.J2 | length 3.8
  Top Layer w0.203: U3.H1@21.668,33.888 v1(22.068,34.288) ; v1@22.08,34.315 22.08,34.301 U3.J2@22.468,34.688
  Bottom Layer w0.203: C37.2@21.832,33.586 22.056,33.586 C37.2@22.068,33.597 ; v1@22.08,34.315 v1@22.148,34.315
  Bottom Layer w0.254: C37.2@22.068,33.597 v1(22.068,34.288) 22.818,34.288 B4.2@23.504,34.974
D3V3_D: B2.2 B4.1 B6.2 C29.1 C31.1 C33.1 C34.2 C35.1 C53.1 JP1.1 KEY2.2 R13.2 R14.2 R15.2 R16.2 R17.2 R18.1 R19.1 R20.1 R25.2 R30.2 R35.2 U3.C3 U3.D4 U3.D7 U3.E2 U3.E3 U3.E6 U3.F3 U3.F5 U3.G3 U3.H8 U3.J3 U3.K5 U3.K7 U3.K9 U11.4 | length 161.2
  Top Layer w0.203: JP1.1@3.372,62.159 5.772,59.759 v1(5.772,55.874) ; U3.C3@17.668,35.488 U3.D4@18.468,36.288 U3.E3@19.268,35.488 19.636,35.488 ; U3.D7@18.468,38.688 U3.E6@19.268,37.888 U3.F5@20.068,37.088 ; U3.E2@19.268,34.688 19.636,35.057 19.636,35.488 ; U3.G3@20.868,35.488 U3.F3@20.068,35.488 19.636,35.488 ; U3.H8@21.668,39.488 v1(22.068,39.088) ; U3.J3@22.468,35.488 v1(22.868,35.888) ; v1(22.868,39.088) U3.K7@23.268,38.688 ; U3.K5@23.268,37.088 v1(23.668,37.488) ; U3.K9@23.268,40.288 v1(23.668,39.888)
  Top Layer w0.254: KEY2.2@6.902,9.255 KEY2.2@12.998,9.255 ; R30.2@14.416,33.692 v1(14.416,34.158) R15.2@14.416,34.63 ; R13.2@19.097,12.068 14.265,12.068 12.998,10.802 KEY2.2@12.998,9.255 ; R14.2@29.331,12.055 32.862,12.055 33.729,11.188 33.729,9.55 34.395,8.884 ; R17.2@36.581,8.884 R16.2@35.158,8.884 34.395,8.884 ; KEY2.2@12.998,9.255 13.493,9.255 14.454,8.293 33.803,8.293 34.395,8.884
  Top Layer w0.305: U11.4@10.548,32.942 10.548,32.809 v1(11.07,32.288) 11.07,31.83 C29.1@11.051,31.811 ; R19.1@27.583,38.39 27.605,38.413 v1(27.605,39.743) ; v1(27.604,42.339) 27.604,42.771 27.612,42.779 R25.2@27.612,41.895 ; v1(28.726,48.738) 28.726,48.755 B2.2@29.211,49.241
  Signal Layer 2 w0.254: v1(8.878,9.263) 8.878,14.675 8.12,15.433 8.12,20.723 14.416,27.018 v1(14.416,34.158)
  Bottom Layer w0.203: v1@5.772,55.874 7.308,55.874 9.449,53.733 9.449,46.536 14.152,41.832 14.152,39.805 R18.1@18.062,35.895 17.315,35.149 15.407,35.149 v1(14.416,34.158) 12.546,32.288 v1(11.07,32.288) ; C33.1@18.858,37.491 C33.1@18.861,37.488 ; C34.2@23.639,39.088 C34.2@23.668,39.117
  Bottom Layer w0.254: R18.1@18.062,35.895 18.068,35.888 v1(18.868,35.888) ; v1(19.668,37.488) 18.861,37.488 18.868,37.481 v1(18.868,35.888) ; 20.428,33.633 20.395,33.666 20.395,35.888 ; v1(22.068,39.088) v1(22.868,39.088) C34.2@23.639,39.088 ; v1(27.605,39.743) v1(27.605,39.743) 27.293,39.431 26.702,39.431 26.245,39.888 v1(23.668,39.888) 23.668,39.117 v1(23.668,37.488) 23.668,35.882 B4.1@23.659,35.874 22.882,35.874 v1(22.868,35.888) 20.395,35.888 ; v1(18.868,35.888) 20.395,35.888
  Bottom Layer w0.305: 20.428,33.633 C53.1@21.051,33.633 ; v1(27.605,39.743) v1(27.604,42.339) 28.726,43.461 v1(28.726,48.738)
DACD: U3.K10 U9.6 | length 19.1
  Top Layer w0.203: U3.K10@23.268,41.088 23.668,41.488 v1(23.668,41.501) ; U9.6@36.43,42.344 38.014,42.344 v1(38.227,42.557)
  Signal Layer 1 w0.152: v1(23.668,41.501) 23.68,41.488 24.222,41.488 24.825,42.091 24.825,42.899 25.456,43.53 26.3,43.53 26.716,43.946 36.47,43.946 37.859,42.557 v1(38.227,42.557)
DC5V: DC5V.1 P7.1 | length 2.9
  Top Layer w0.8: P7.1@40.834,65.676 DC5V.1@43.704,65.676
DIO1: U3.B7 | length 0.6
  Top Layer w0.203: v2(16.468,39.088) U3.B7@16.868,38.688
DIO2: U3.A7 | length 0.5
  Top Layer w0.203: v2(15.689,39.039) 15.717,39.039 U3.A7@16.068,38.688
DIO3: U3.B8 | length 0.5
  Top Layer w0.203: v2(16.512,39.861) 16.512,39.844 U3.B8@16.868,39.488 U3.B8@16.866,39.488
EECLK: R15.1 U3.A2 U11.1 | length 4.6
  Top Layer w0.152: R15.1@13.515,34.631 14.139,35.255 14.759,35.255 15.325,34.688 U3.A2@16.068,34.688
  Top Layer w0.203: U11.1@12.448,35.342 12.448,35.061 12.872,34.637 13.508,34.637 R15.1@13.515,34.631
EEDAT: R30.1 U3.A1 U11.3 | length 7.2
  Top Layer w0.152: R30.1@13.515,33.691 14.146,33.06 14.762,33.06 15.591,33.888 U3.A1@16.068,33.888
  Top Layer w0.203: U11.3@10.548,35.342 10.548,34.589 11.058,34.079 13.127,34.079 R30.1@13.515,33.691
EN0: C23.1 CH1.1 R35.1 U3.M12 | length 42.9
  Top Layer w0.152: U3.M12@24.868,42.688 25.106,42.927 25.916,42.927 v1(26.068,42.775) 26.694,42.775 R35.1@26.698,42.779 ; R35.1@26.549,42.927 R35.1@26.673,42.804
  Top Layer w0.254: R35.1@26.673,42.804 R35.1@26.698,42.779
  Signal Layer 2 w0.152: v1(26.426,47.136) 26.421,47.142 26.421,47.626 26.955,48.16 26.955,70.981 30.243,74.269 v1(30.243,79.256)
  Bottom Layer w0.152: v1(26.068,42.775) 26.375,43.082 26.375,47.086 v1(26.426,47.136)
  Bottom Layer w0.254: CH1.1@30.242,80.916 v1(30.243,79.256) C23.1@30.804,78.694
EN1: C21.1 CH1.3 R25.1 U3.M11 | length 45.8
  Top Layer w0.152: U3.M11@24.868,41.888 25.329,41.888 25.484,41.733 26.535,41.733 R25.1@26.698,41.895
  Top Layer w0.254: R25.1@26.698,41.895 26.702,41.891 v1(26.702,41.411)
  Signal Layer 2 w0.152: v1(26.941,46.765) 26.919,46.786 26.919,47.693 27.283,48.057 27.283,70.859 30.567,74.143 30.567,75.535 v1(34.242,79.211)
  Bottom Layer w0.152: v1(26.702,41.411) 26.702,46.526 v1(26.941,46.765)
  Bottom Layer w0.254: C21.1@33.725,78.694 v1(34.242,79.211) CH1.3@34.242,80.916
G_LED: DS1.2 U3.M3 | length 28.1
  Top Layer w0.203: U3.M3@24.868,35.488 25.184,35.488 26.001,34.671 26.974,34.671 28.08,33.565 28.08,24.389 31.313,21.156 31.313,16.296 DS1.2@35.158,12.451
